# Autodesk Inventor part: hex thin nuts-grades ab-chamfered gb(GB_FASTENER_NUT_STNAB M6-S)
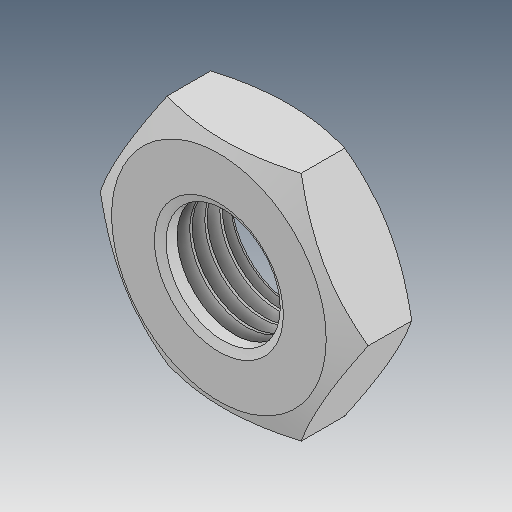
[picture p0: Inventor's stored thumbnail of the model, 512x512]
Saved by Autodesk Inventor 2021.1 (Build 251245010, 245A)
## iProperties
Created: 2019-12
Part Number: hex thin nuts-grades ab-chamfered gb(GB_FASTENER_NUT_STNAB M6-S)
Material: Ogólny
Document SubType Name: Modeling
Designer: user
Density: 1 g/cm^3
Appearance: Domyślna
Author: user
Revision Number: ÈÎºÎ
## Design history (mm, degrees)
feature "ÊäÈë1"
node "Bryła1"
